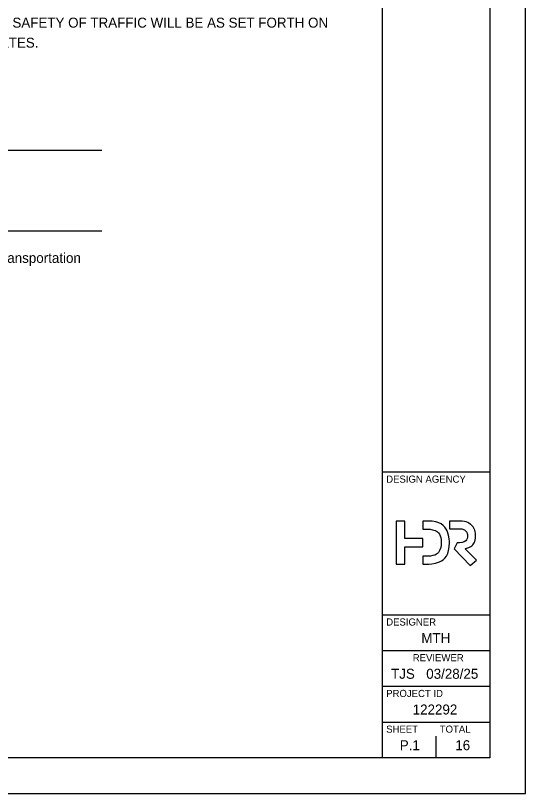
# Model space of a CAD drawing. Extents: x 0 to 34, y 0 to 22.
# Drawn here: x 26.86 to 34, y 0 to 10.89 of the extents above; entities that cross this region are included whole.
import ezdxf

# ---------------------------------------------------------------- set-up
doc = ezdxf.new("R2010")
doc.units = 0
for name, color, linetype in [('SH_Border', 7, 'Continuous'), ('SH_Cut_Line', 7, 'Continuous'), ('SH_Data', 7, 'Continuous'), ('SH_Text', 7, 'Continuous')]:
    doc.layers.add(name, color=color, linetype=linetype)

msp = doc.modelspace()

# ---------------------------------------------------------------- linework, layer by layer
at = {"layer": 'SH_Border'}
for p, q in [((32, 0.5), (32, 21.5)), ((32, 4.5), (33.5, 4.5)), ((32, 2.5), (33.5, 2.5)), ((32, 2), (33.5, 2)), ((32, 1.5), (33.5, 1.5)), ((32, 1), (33.5, 1))]:
    msp.add_line(p, q, dxfattribs=at)
msp.add_lwpolyline([(1.5, 21.5), (33.5, 21.5), (33.5, 0.5), (1.5, 0.5)], close=True, dxfattribs=at)
at = {"layer": 'SH_Cut_Line'}
msp.add_lwpolyline([(0, 0), (34, 0), (34, 22), (0, 22)], close=True, dxfattribs=at)
at = {"layer": 'SH_Data'}
for p, q in [((24.57, 9.007), (28.07, 9.007)), ((24.57, 7.877), (28.07, 7.877)), ((32.75, 3.5), (32.75, 3.5)), ((32.75, 0.5), (32.75, 0.8)), ((32.375, 0.675), (32.375, 0.675))]:
    msp.add_line(p, q, dxfattribs=at)
msp.add_lwpolyline([(32.565, 3.571), (32.311, 3.571), (32.311, 3.813), (32.189, 3.813), (32.189, 3.209), (32.311, 3.209), (32.311, 3.451), (32.565, 3.451)], close=True, dxfattribs=at)
for points in [[(32.634, 3.813), (32.562, 3.813), (32.562, 3.7), (32.634, 3.7)], [(33.063, 3.813), (32.935, 3.813), (32.935, 3.704), (33.072, 3.704)], [(32.936, 3.511), (32.936, 3.511), (32.936, 3.511), (32.936, 3.512), (32.936, 3.512)], [(33.077, 3.51), (33.043, 3.51), (33.003, 3.424), (33.226, 3.192), (33.313, 3.265), (33.155, 3.425)], [(32.634, 3.322), (32.562, 3.322), (32.562, 3.209), (32.634, 3.209)]]:
    msp.add_lwpolyline(points, dxfattribs=at)
for points in [[(32.936, 3.512), (32.936, 3.512), (32.935, 3.686), (32.808, 3.813), (32.634, 3.813)], [(33.239, 3.759), (33.239, 3.759), (33.193, 3.802), (33.141, 3.813), (33.063, 3.813)], [(33.072, 3.704), (33.072, 3.704), (33.113, 3.704), (33.141, 3.696), (33.161, 3.676)], [(33.302, 3.605), (33.302, 3.605), (33.302, 3.668), (33.284, 3.716), (33.239, 3.759)], [(32.634, 3.7), (32.634, 3.7), (32.744, 3.7), (32.822, 3.622), (32.822, 3.511)], [(33.189, 3.607), (33.189, 3.607), (33.189, 3.546), (33.136, 3.51), (33.077, 3.51)], [(33.155, 3.425), (33.155, 3.425), (33.242, 3.441), (33.302, 3.521), (33.302, 3.605)], [(33.161, 3.676), (33.161, 3.676), (33.179, 3.658), (33.189, 3.634), (33.189, 3.607)], [(32.822, 3.511), (32.822, 3.511), (32.822, 3.4), (32.744, 3.322), (32.634, 3.322)], [(32.634, 3.209), (32.634, 3.209), (32.808, 3.209), (32.935, 3.336), (32.936, 3.511)]]:
    msp.add_open_spline(points, degree=3, dxfattribs=at)

# ---------------------------------------------------------------- texts
for s, height, p in [('DESIGN AGENCY', 0.1, (32.05, 4.35)), ('DESIGNER', 0.1, (32.05, 2.35)), ('MTH', 0.14, (32.542, 2.105)), ('REVIEWER', 0.1, (32.422, 1.85)), ('TJS', 0.14, (32.118, 1.605)), ('03/28/25', 0.14, (32.611, 1.605)), ('PROJECT ID', 0.1, (32.05, 1.35)), ('122292', 0.14, (32.421, 1.105)), ('SHEET', 0.1, (32.05, 0.85)), ('TOTAL', 0.1, (32.8, 0.85)), ('P.1', 0.14, (32.24, 0.605)), ('16', 0.14, (33.018, 0.605))]:
    msp.add_text(s, height=height, dxfattribs=at).set_placement(p)
at = {"layer": 'SH_Text'}
for s, p in [('THE MAINTENANCE AND SAFETY OF TRAFFIC WILL BE AS SET FORTH ON ', (24.528, 10.72)), ('THE PLANS AND ESTIMATES.', (24.528, 10.44)), ('Director, Department of Transportation', (24.57, 7.427))]:
    msp.add_text(s, height=0.14, dxfattribs=at).set_placement(p)

doc.saveas('drawing.dxf')
